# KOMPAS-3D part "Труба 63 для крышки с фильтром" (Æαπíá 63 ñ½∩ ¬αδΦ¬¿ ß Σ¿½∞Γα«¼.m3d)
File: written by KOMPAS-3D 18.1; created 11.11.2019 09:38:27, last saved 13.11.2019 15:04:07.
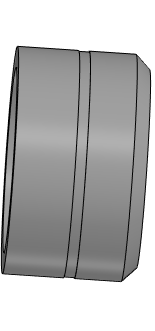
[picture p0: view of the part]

Document properties: Полное имя файла: D:\Magna\Магна Ins\Магна ins 10\М10-00.00.000\3Д\Труба 63 для крышки с фильтром.m3d

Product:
- Part/product: Труба 63 для крышки с фильтром
    Масса: 0.37176

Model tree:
1. Эскиз:2  (with: Элемент выдавливания:1, Элемент выдавливания:3)  (labels: Труба 63 для крышки с фильтром)
2. Элемент выдавливания:1
     Расстояние 1 = 17; Расстояние 2 = 20
3. Смещенная плоскость:1  (with: Элемент выдавливания:1)
     Расстояние = 17
4. Эскиз:3  (with: Элемент выдавливания:1)
5. Фаска:3  (with: Элемент выдавливания:1)
     Угол = 45; Длина 1 = 2.5; Длина 2 = 2.5
6. Элемент выдавливания:3
     Расстояние 2 = 3
7. Условное изображение резьбы:3  (with: Элемент выдавливания:1, Фаска:3, Элемент выдавливания:3)  (labels: M60x3; cil0_24705-2004 fine)
     Длина резьбы = 17; Шаг резьбы = 3; Номинальный диаметр резьбы = 60
8. Подгонка:3  (with: Фаска:3, Элемент выдавливания:1)
9. Эскиз:5  (with: Элемент выдавливания:3)

Referenced files in D:\Magna\Магна Ins\Магна ins 10\М10-00.00.000\3Д\: Труба 1165 для фильтра.a3d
